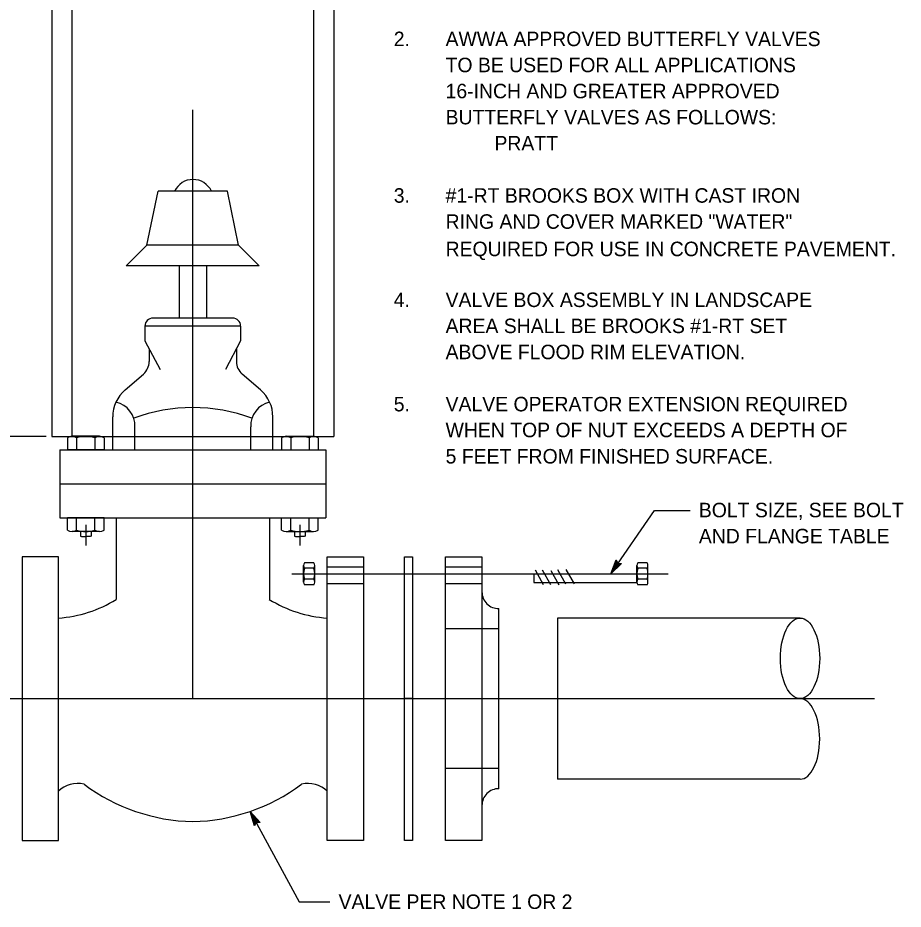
# Model space of a CAD drawing. Extents: x -123486 to -116575, y -107066 to -101122.
# Drawn here: x -119197.1 to -118830.8, y -102463.9 to -102095 of the extents above; entities that cross this region are included whole.
import ezdxf

# ---------------------------------------------------------------- set-up
doc = ezdxf.new("R2010")
doc.units = 0
for name, color, linetype in [('G-MARK', 7, 'Continuous'), ('G-TEXT', 7, 'Continuous'), ('Misc CnstDet(22)', 7, 'Continuous')]:
    doc.layers.add(name, color=color, linetype=linetype)

msp = doc.modelspace()

# ---------------------------------------------------------------- linework, layer by layer
at = {"layer": 'G-MARK'}
msp.add_line((-119185.38, -102268.21), (-119225.34, -102268.21), dxfattribs=at)
for points in [[(-118951.79, -102325.09), (-118933.67, -102298.84), (-118918.88, -102298.84)], [(-119100.99, -102423.44), (-119080.75, -102460.92), (-119068.04, -102460.92)]]:
    msp.add_lwpolyline(points, dxfattribs=at)
at = {"layer": 'G-TEXT'}
for p, q in [((-118951.79, -102325.09), (-118949.58, -102319.36)), ((-118949.58, -102319.36), (-118949.58, -102319.36)), ((-118949.58, -102319.36), (-118948.91, -102320.76)), ((-118947.35, -102320.84), (-118951.79, -102325.09)), ((-118951.03, -102323.93), (-118949.41, -102319.75)), ((-118947.77, -102320.82), (-118951.03, -102323.94)), ((-118950.26, -102322.79), (-118949.22, -102320.09)), ((-118948.2, -102320.82), (-118950.26, -102322.79)), ((-118949.49, -102321.64), (-118949.05, -102320.49)), ((-118948.58, -102320.77), (-118949.49, -102321.64)), ((-118948.91, -102320.76), (-118947.35, -102320.84)), ((-118947.35, -102320.84), (-118947.35, -102320.84)), ((-118951.79, -102325.09), (-118951.79, -102325.09)), ((-119099.22, -102429.33), (-119100.99, -102423.44)), ((-119100.99, -102423.44), (-119100.99, -102423.44)), ((-119100.99, -102423.44), (-119096.89, -102428.02)), ((-119099.02, -102428.96), (-119100.32, -102424.64)), ((-119100.31, -102424.65), (-119097.32, -102427.99)), ((-119098.82, -102428.58), (-119099.64, -102425.85)), ((-119099.64, -102425.85), (-119097.71, -102428.01)), ((-119098.44, -102427.97), (-119099.22, -102429.33)), ((-119099.22, -102429.33), (-119099.22, -102429.33)), ((-119098.6, -102428.26), (-119098.96, -102427.05)), ((-119098.96, -102427.05), (-119098.14, -102427.98)), ((-119096.89, -102428.02), (-119098.44, -102427.97)), ((-119096.89, -102428.02), (-119096.89, -102428.02))]:
    msp.add_line(p, q, dxfattribs=at)
at = {"layer": 'Misc CnstDet(22)'}
for p, q in [((-119183.04, -101893.21), (-119183.04, -102268.21)), ((-119066.38, -101893.21), (-119066.38, -102268.21)), ((-119174.71, -101930.92), (-119174.71, -102268.21)), ((-119074.71, -101930.92), (-119074.71, -102268.21)), ((-119124.71, -102376.76), (-119124.71, -102133.01)), ((-119143.67, -102189.05), (-119139.09, -102166.76)), ((-119110.34, -102166.76), (-119139.09, -102166.76)), ((-119105.75, -102189.05), (-119110.34, -102166.76)), ((-119143.67, -102189.05), (-119152.21, -102197.59)), ((-119105.75, -102189.05), (-119143.67, -102189.05)), ((-119105.75, -102189.05), (-119097.21, -102197.59)), ((-119097.21, -102197.59), (-119152.21, -102197.59)), ((-119130.34, -102197.59), (-119130.34, -102219.26)), ((-119119.09, -102197.59), (-119119.09, -102219.26)), ((-119108.25, -102219.26), (-119141.17, -102219.26)), ((-119104.92, -102222.59), (-119144.5, -102222.59)), ((-119144.5, -102222.59), (-119144.5, -102228.63)), ((-119104.92, -102222.59), (-119104.92, -102228.63)), ((-119144.5, -102228.63), (-119138.25, -102240.51)), ((-119104.92, -102228.63), (-119111.17, -102240.51)), ((-119142.77, -102231.93), (-119142.77, -102237.27)), ((-119106.65, -102231.93), (-119106.65, -102237.27)), ((-119152.7, -102248.96), (-119145.12, -102242.41)), ((-119096.72, -102248.96), (-119104.3, -102242.41)), ((-119157.84, -102273.84), (-119157.84, -102260.18)), ((-119091.59, -102273.84), (-119091.59, -102260.18)), ((-119183.04, -102268.21), (-119066.38, -102268.21)), ((-119176.58, -102268.76), (-119176.58, -102273.83)), ((-119163.32, -102268.2), (-119174.68, -102268.2)), ((-119172.79, -102268.76), (-119172.79, -102273.83)), ((-119165.21, -102268.76), (-119165.21, -102273.83)), ((-119161.42, -102268.76), (-119161.42, -102273.83)), ((-119087.99, -102268.76), (-119087.99, -102273.83)), ((-119086.1, -102268.2), (-119074.73, -102268.2)), ((-119084.21, -102268.76), (-119084.21, -102273.83)), ((-119076.63, -102268.76), (-119076.63, -102273.83)), ((-119072.84, -102268.76), (-119072.84, -102273.83)), ((-119179.71, -102273.84), (-119069.71, -102273.84)), ((-119179.71, -102273.84), (-119179.71, -102301.96)), ((-119161.42, -102273.83), (-119176.58, -102273.83)), ((-119087.99, -102273.83), (-119072.84, -102273.83)), ((-119069.71, -102273.84), (-119069.71, -102301.96)), ((-119179.71, -102287.9), (-119069.71, -102287.9)), ((-119179.71, -102301.96), (-119069.71, -102301.96)), ((-119161.42, -102301.95), (-119176.58, -102301.95)), ((-119176.58, -102307.01), (-119176.58, -102301.95)), ((-119172.79, -102307.01), (-119172.79, -102301.95)), ((-119165.21, -102307.01), (-119165.21, -102301.95)), ((-119161.42, -102307.01), (-119161.42, -102301.95)), ((-119156.38, -102301.96), (-119156.38, -102335.71)), ((-119093.04, -102301.96), (-119093.04, -102335.71)), ((-119087.99, -102301.95), (-119072.84, -102301.95)), ((-119087.99, -102307.01), (-119087.99, -102301.95)), ((-119084.21, -102307.01), (-119084.21, -102301.95)), ((-119076.63, -102307.01), (-119076.63, -102301.95)), ((-119072.84, -102307.01), (-119072.84, -102301.95)), ((-119163.32, -102307.57), (-119174.68, -102307.57)), ((-119169.01, -102304.88), (-119169.01, -102313.42)), ((-119086.1, -102307.57), (-119074.73, -102307.57)), ((-119080.41, -102304.88), (-119080.41, -102313.42)), ((-119078.86, -102328.5), (-119078.86, -102321.68)), ((-119074.62, -102320.55), (-119078.52, -102320.55)), ((-119074.62, -102322.82), (-119078.52, -102322.82)), ((-119074.28, -102328.5), (-119074.28, -102321.68)), ((-119069.09, -102322.17), (-119054.09, -102322.17)), ((-119020.13, -102322.17), (-119005.13, -102322.17)), ((-118940.97, -102328.5), (-118940.97, -102321.68)), ((-118936.72, -102320.55), (-118940.63, -102320.55)), ((-118936.72, -102322.82), (-118940.63, -102322.82)), ((-118936.39, -102328.5), (-118936.39, -102321.68)), ((-119083.67, -102325.09), (-118928.04, -102325.09)), ((-118983.67, -102325.09), (-118983.67, -102328.63)), ((-118983.04, -102323.42), (-118979.71, -102329.46)), ((-118980.11, -102323.47), (-118976.78, -102329.51)), ((-118976.57, -102323.68), (-118973.24, -102329.72)), ((-118973.86, -102323.26), (-118970.53, -102329.3)), ((-118970.32, -102323.26), (-118966.99, -102329.3)), ((-119074.62, -102327.37), (-119078.52, -102327.37)), ((-119074.62, -102329.64), (-119078.52, -102329.64)), ((-119069.09, -102329.05), (-119054.09, -102329.05)), ((-119020.13, -102329.05), (-119005.13, -102329.05)), ((-118983.67, -102328.63), (-118940.95, -102328.63)), ((-118936.72, -102327.37), (-118940.63, -102327.37)), ((-118936.72, -102329.64), (-118940.63, -102329.64)), ((-118998.04, -102414.04), (-118998.04, -102339.47)), ((-118873.46, -102343.42), (-118973.88, -102343.42)), ((-118973.88, -102343.42), (-118973.88, -102410.09)), ((-118998.04, -102347.8), (-119020.13, -102347.8)), ((-119375.96, -102376.76), (-118842.63, -102376.76)), ((-118998.04, -102405.71), (-119020.13, -102405.71)), ((-118873.46, -102410.09), (-118973.88, -102410.09))]:
    msp.add_line(p, q, dxfattribs=at)
for points in [[(-119148.67, -102273.84), (-119148.67, -102264.26)], [(-119100.75, -102273.84), (-119100.75, -102264.26)], [(-119171.22, -102307.59), (-119171.22, -102309.46), (-119170.81, -102309.67), (-119169.01, -102309.67)], [(-119166.79, -102307.59), (-119166.79, -102309.46), (-119167.21, -102309.67), (-119169.01, -102309.67)], [(-119082.63, -102307.59), (-119082.63, -102309.46), (-119082.21, -102309.67), (-119080.41, -102309.67)], [(-119078.2, -102307.59), (-119078.2, -102309.46), (-119078.61, -102309.67), (-119080.41, -102309.67)], [(-119033.77, -102318.01), (-119033.77, -102376.76), (-119037.11, -102376.76), (-119037.11, -102318.01), (-119033.77, -102318.01)], [(-119037.11, -102435.51), (-119037.11, -102376.76), (-119033.77, -102376.76), (-119033.77, -102435.51), (-119037.11, -102435.51)]]:
    msp.add_lwpolyline(points, dxfattribs=at)
for points in [[(-119195.34, -102435.51), (-119180.34, -102435.51), (-119180.34, -102318.01), (-119195.34, -102318.01)], [(-119054.09, -102435.51), (-119069.09, -102435.51), (-119069.09, -102318.01), (-119054.09, -102318.01)], [(-119037.11, -102435.51), (-119037.11, -102318.01), (-119033.77, -102318.01), (-119033.77, -102435.51)], [(-119005.13, -102435.51), (-119020.13, -102435.51), (-119020.13, -102318.01), (-119005.13, -102318.01)]]:
    msp.add_lwpolyline(points, close=True, dxfattribs=at)
for centre, radius, start, end in [((-119124.61, -102170.27), 8.38, 24.8202, 155.1798), ((-119141.17, -102222.59), 3.33, 90, 180), ((-119108.25, -102222.59), 3.33, 0, 90), ((-119149.56, -102237.27), 6.79, 310.8151, 0), ((-119099.86, -102237.27), 6.79, 180, 229.1849), ((-119143.02, -102260.18), 14.82, 130.8151, 180), ((-119106.41, -102260.18), 14.82, 0, 49.1849), ((-119158.77, -102263.86), 10.11, 357.754, 76.9636), ((-119124.71, -102327), 70.69, 69.7517, 110.2483), ((-119090.65, -102263.86), 10.11, 103.0364, 182.246), ((-119174.68, -102271.69), 3.49, 57.1328, 122.8672), ((-119169, -102281.33), 13.12, 73.2214, 106.7787), ((-119163.32, -102271.69), 3.49, 57.1328, 122.8672), ((-119086.1, -102271.69), 3.49, 57.1328, 122.8672), ((-119080.42, -102281.33), 13.12, 73.2214, 106.7786), ((-119074.73, -102271.69), 3.49, 57.1328, 122.8672), ((-119174.68, -102304.08), 3.49, 237.1328, 302.8672), ((-119169, -102294.45), 13.12, 253.2214, 286.7787), ((-119163.32, -102304.08), 3.49, 237.1328, 302.8672), ((-119086.1, -102304.08), 3.49, 237.1328, 302.8672), ((-119080.42, -102294.45), 13.12, 253.2214, 286.7787), ((-119074.73, -102304.08), 3.49, 237.1328, 302.8672), ((-119076.76, -102321.68), 2.09, 147.1328, 212.8672), ((-119070.98, -102325.09), 7.87, 163.2214, 196.7787), ((-119076.38, -102321.68), 2.09, 327.1328, 32.8672), ((-119082.16, -102325.09), 7.87, 343.2214, 16.7787), ((-118938.87, -102321.68), 2.09, 147.1328, 212.8672), ((-118933.09, -102325.09), 7.87, 163.2214, 196.7787), ((-118938.48, -102321.68), 2.09, 327.1328, 32.8672), ((-118944.26, -102325.09), 7.87, 343.2214, 16.7787), ((-119076.76, -102328.5), 2.09, 147.1328, 212.8672), ((-119076.38, -102328.5), 2.09, 327.1328, 32.8672), ((-118938.87, -102328.5), 2.09, 147.1328, 212.8672), ((-118938.48, -102328.5), 2.09, 327.1328, 32.8672), ((-118998.17, -102332.57), 6.9, 180, 271.0419), ((-119184.05, -102290.77), 52.78, 274.0412, 301.6288), ((-119065.37, -102290.77), 52.78, 238.3712, 265.9588), ((-119172.42, -102423.12), 11.28, 76.1013, 134.599), ((-119123.36, -102350.35), 77.27, 233.1354, 268.9958), ((-119126.06, -102350.35), 77.27, 271.0042, 306.8646), ((-119077, -102423.12), 11.28, 45.401, 103.8987), ((-118998.17, -102420.94), 6.9, 88.9581, 180)]:
    msp.add_arc(centre, radius, start, end, dxfattribs=at)
msp.add_ellipse((-118873.46, -102360.09), major_axis=(0, 16.67), ratio=0.4875, dxfattribs=at)
msp.add_ellipse((-118873.46, -102393.42), major_axis=(0, 16.67), ratio=0.4875, start_param=3.141593, end_param=6.283185, dxfattribs=at)

# ---------------------------------------------------------------- texts
for s, p in [('2.', (-119041.57, -102106.72)), ('AWWA APPROVED BUTTERFLY VALVES', (-119020.12, -102106.72)), ('TO BE USED FOR ALL APPLICATIONS', (-119020.12, -102117.51)), ('16-INCH AND GREATER APPROVED', (-119020.12, -102128.3)), ('BUTTERFLY VALVES AS FOLLOWS:', (-119020.12, -102139.1)), ('PRATT', (-118999.91, -102149.89)), ('3.', (-119041.57, -102171.51)), ('#1-RT BROOKS BOX WITH CAST IRON', (-119020.12, -102171.51)), ('RING AND COVER MARKED "WATER"', (-119020.12, -102182.31)), ('REQUIRED FOR USE IN CONCRETE PAVEMENT.', (-119020.12, -102193.64)), ('4.', (-119041.57, -102214.69)), ('VALVE BOX ASSEMBLY IN LANDSCAPE', (-119020.12, -102214.69)), ('AREA SHALL BE BROOKS #1-RT SET', (-119020.12, -102225.48)), ('ABOVE FLOOD RIM ELEVATION.', (-119020.12, -102236.28)), ('5.', (-119041.57, -102257.86)), ('VALVE OPERATOR EXTENSION REQUIRED', (-119020.12, -102257.86)), ('WHEN TOP OF NUT EXCEEDS A DEPTH OF', (-119020.12, -102268.57)), ('5 FEET FROM FINISHED SURFACE.', (-119020.12, -102279.45)), ('BOLT SIZE, SEE BOLT', (-118915.34, -102301.7)), ('AND FLANGE TABLE', (-118915.34, -102312.49)), ('VALVE PER NOTE 1 OR 2', (-119064.39, -102463.8))]:
    msp.add_text(s, height=6, dxfattribs=at).set_placement(p)

doc.saveas('drawing.dxf')
